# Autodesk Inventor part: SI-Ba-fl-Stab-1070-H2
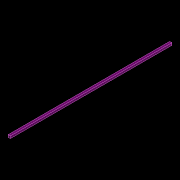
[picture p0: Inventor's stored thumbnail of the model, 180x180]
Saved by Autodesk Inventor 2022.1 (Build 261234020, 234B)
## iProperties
Part Number: SI-Ba-fl-Stab-1070-H2
Material: Allgemein
Document SubType Name: Modellieren
Designer: joachim
Appearance: Vorgabe
Author: joachim
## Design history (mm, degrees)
sketch "Skizze1"
  geometry: L1 (0, 0)-(15, 0); L2 (15, 0)-(15, 15); L3 (15, 15)-(0, 15); L4 (0, 15)-(0, 0)
  constraints: 8 end point, 2 parallel, 1 horizontal, 1 perpendicular
  dimensions: "d0" = 15 distance of L3.end L2.end; "d1" = 15 distance of L2.end L1.end
extrude "Extrusion1" new body sketch "Skizze1" distance "d2" = 1070; taper "d3" = 0 deg
node "Volumenkörper1"
node "Volumenkörper"
node "Flächenkörper"
